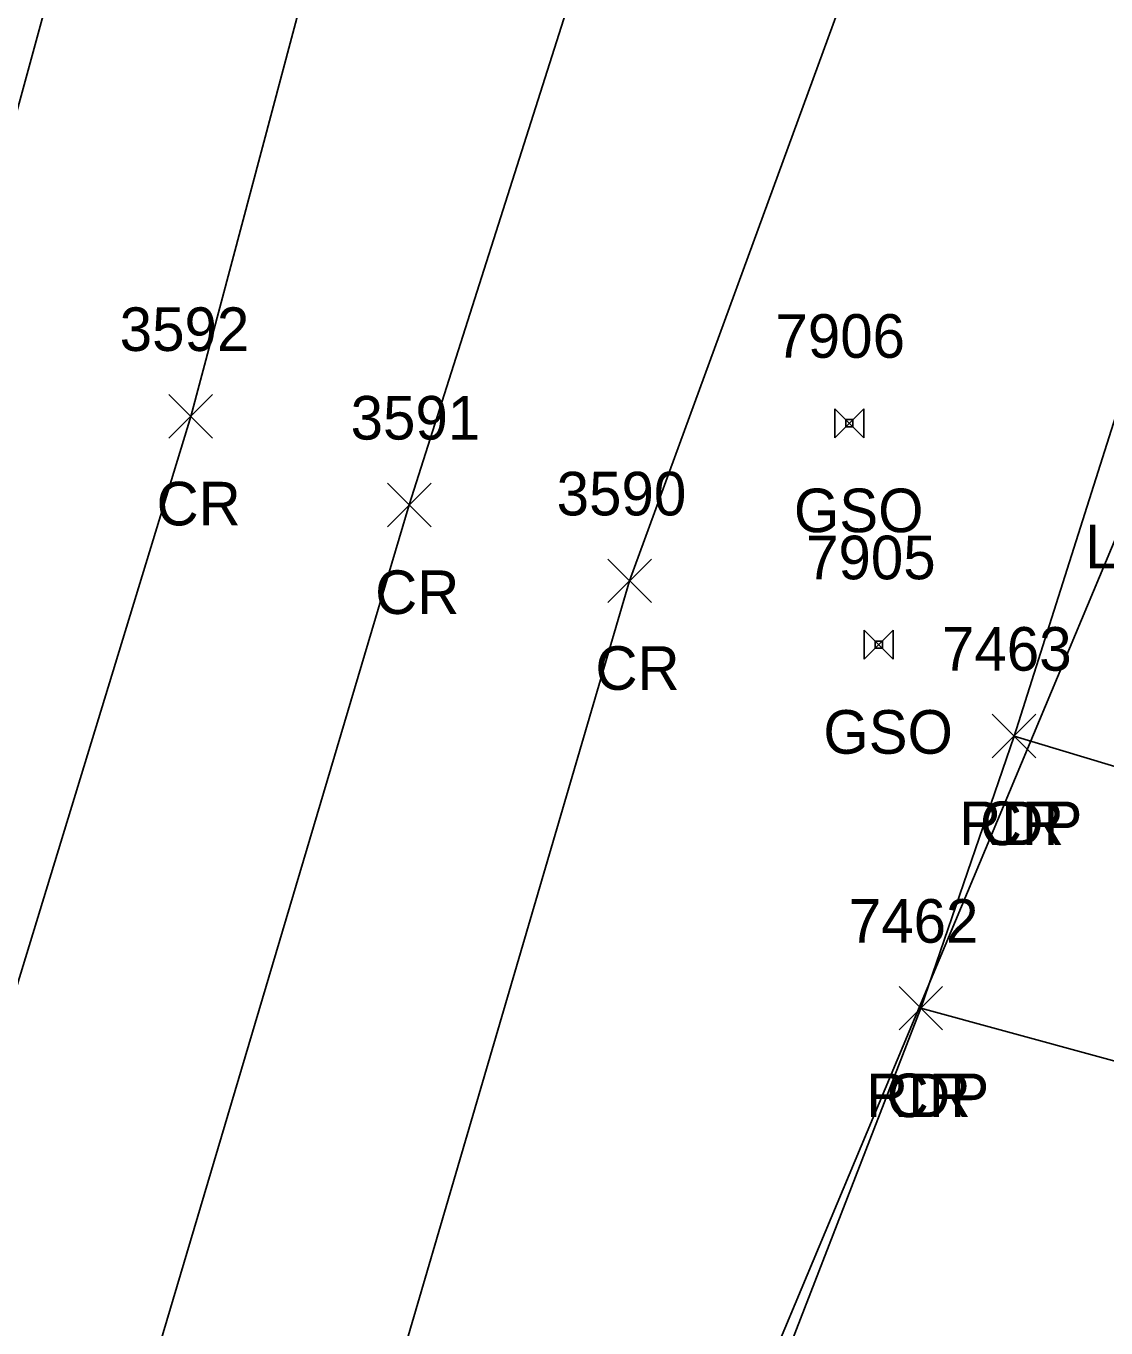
# Model space of a CAD drawing. Extents: x 1462089 to 1464015, y 730534 to 736144.
# Drawn here: x 1462888.4 to 1462938, y 732362.7 to 732422.4 of the extents above; entities that cross this region are included whole.
import ezdxf

# ---------------------------------------------------------------- set-up
doc = ezdxf.new("R2010")
doc.units = 0
for name, color, linetype in [('DCP', 7, 'Continuous'), ('P_A', 7, 'Continuous'), ('P_I', 7, 'Continuous'), ('P_TIC', 7, 'Continuous'), ('PET', 7, 'Continuous'), ('PRC', 7, 'Continuous'), ('S_C', 7, 'Continuous'), ('U_A', 7, 'Continuous'), ('U_I', 7, 'Continuous'), ('UGV', 7, 'Continuous')]:
    doc.layers.add(name, color=color, linetype=linetype)

msp = doc.modelspace()

# ---------------------------------------------------------------- linework, layer by layer
at = {"layer": 'DCP'}
msp.add_lwpolyline([(1462904.683, 732318.359), (1462942.289, 732408.157)], dxfattribs=at)
at = {"layer": 'P_TIC'}
for points in [[(1462894.983, 732403.526), (1462896.983, 732405.526)], [(1462896.983, 732403.526), (1462894.983, 732405.526)], [(1462894.983, 732403.526), (1462896.983, 732405.526)], [(1462896.983, 732403.526), (1462894.983, 732405.526)], [(1462905.012, 732399.463), (1462907.012, 732401.463)], [(1462907.012, 732399.463), (1462905.012, 732401.463)], [(1462905.012, 732399.463), (1462907.012, 732401.463)], [(1462907.012, 732399.463), (1462905.012, 732401.463)], [(1462915.118, 732395.984), (1462917.118, 732397.984)], [(1462917.118, 732395.984), (1462915.118, 732397.984)], [(1462915.118, 732395.984), (1462917.118, 732397.984)], [(1462917.118, 732395.984), (1462915.118, 732397.984)], [(1462932.758, 732388.862), (1462934.758, 732390.862)], [(1462934.758, 732388.862), (1462932.758, 732390.862)], [(1462932.758, 732388.862), (1462934.758, 732390.862)], [(1462934.758, 732388.862), (1462932.758, 732390.862)], [(1462928.482, 732376.385), (1462930.482, 732378.385)], [(1462930.482, 732376.385), (1462928.482, 732378.385)], [(1462928.482, 732376.385), (1462930.482, 732378.385)], [(1462930.482, 732376.385), (1462928.482, 732378.385)]]:
    msp.add_lwpolyline(points, dxfattribs=at)
at = {"layer": 'PET'}
msp.add_lwpolyline([(1462879.385, 732206.829), (1462892.219, 732254.305), (1462907.579, 732309.882), (1462913.989, 732337.713), (1462917.604, 732346.713), (1462929.482, 732377.385), (1462933.758, 732389.862), (1462941.672, 732414.763), (1462948.84, 732435.879), (1462965.82, 732486.157), (1462974.322, 732513.603), (1462985.987, 732551.34), (1462997.312, 732587.459), (1463010.568, 732628.542), (1463018.12, 732655.414), (1463023.478, 732670.997), (1463036.185, 732713.313)], dxfattribs=at)
at = {"layer": 'PRC'}
for points in [[(1463184.256, 733428.992), (1463177.497, 733386.208), (1463169.424, 733335.001), (1463162.872, 733301.128), (1463154.541, 733254.523), (1463145.288, 733216.479), (1463131.667, 733162.646), (1463112.818, 733093.24), (1463099.084, 733044.738), (1463082.496, 732993.09), (1463066.926, 732944.788), (1463054.224, 732905.139), (1463038.504, 732856.129), (1463025.084, 732814.554), (1463009.903, 732766.247), (1462997.491, 732727.734), (1462980.345, 732670.554), (1462968.817, 732637.254), (1462956.141, 732592.493), (1462943.226, 732555.631), (1462933.854, 732526.131), (1462921.414, 732485.157), (1462905.691, 732440.942), (1462895.983, 732404.526)], [(1463173.556, 733299.02), (1463165.514, 733252.575), (1463157.364, 733210.847), (1463147.481, 733159.84), (1463128.564, 733086.33), (1463116.128, 733039.218), (1463100.451, 732983.575), (1463087.947, 732938.839), (1463073.799, 732896.756), (1463059.596, 732849.778), (1463047.555, 732806.211), (1463032.361, 732758.169), (1463016.832, 732714.699), (1463001.87, 732663.361), (1462991.082, 732629.319), (1462977.348, 732584.698), (1462966.059, 732548.545), (1462956.48, 732518.599), (1462941.542, 732474.035), (1462928.099, 732429.753), (1462916.118, 732396.984)], [(1463154.541, 733254.523), (1463146.614, 733215.85), (1463135.444, 733161.471), (1463118.39, 733090.76), (1463105.826, 733042.869), (1463089.368, 732989.244), (1463076.43, 732943.443), (1463063.883, 732901.539), (1463049.781, 732852.757), (1463036.576, 732810.581), (1463021.663, 732763.563), (1463007.349, 732718.699), (1462991.106, 732667.436), (1462980.417, 732633.719), (1462966.431, 732588.152), (1462955.049, 732551.986), (1462945.505, 732521.937), (1462931.545, 732478.169), (1462917.136, 732435.424), (1462906.012, 732400.463)], [(1462985.716, 732731.928), (1462969.444, 732677.267), (1462957.486, 732641.208), (1462943.904, 732597.669), (1462931.653, 732559.608), (1462922.759, 732531.119), (1462910.18, 732489.033), (1462895.07, 732444.402), (1462885.161, 732408.132), (1462864.593, 732375.333), (1462853.42, 732347.258), (1462832.874, 732276.651), (1462823.233, 732232.908), (1462808.463, 732182.81), (1462796.537, 732136.818), (1462784.674, 732094.481), (1462773.756, 732052.904), (1462761.068, 732007.231), (1462748.947, 731961.516), (1462736.508, 731921.312)], [(1462895.983, 732404.526), (1462883.093, 732362.376), (1462876.352, 732338.992), (1462858.324, 732273.435), (1462845.774, 732225.609), (1462832.163, 732177.159), (1462820.065, 732130.658), (1462807.669, 732084.907), (1462796.727, 732044.248), (1462784.843, 732000.16), (1462772.409, 731954.341), (1462759.38, 731913.09)], [(1462906.012, 732400.463), (1462887.359, 732337.746)], [(1462916.118, 732396.984), (1462897.997, 732335.159), (1462879.045, 732267.64)], [(1462933.758, 732389.862), (1462981.203, 732375.569), (1463025.599, 732361.351), (1463057.397, 732350.23), (1463102.913, 732324.868)], [(1462929.482, 732377.385), (1462978.213, 732364.082), (1463022.056, 732350.159), (1463054.853, 732339.994), (1463102.913, 732324.868), (1463145.703, 732311.685), (1463172.464, 732303.441), (1463219.444, 732289.053), (1463245.294, 732280.954)]]:
    msp.add_lwpolyline(points, dxfattribs=at)
at = {"layer": 'UGV'}
for p, q in [((1462925.536, 732404.88), (1462926.869, 732403.547)), ((1462926.869, 732404.88), (1462925.536, 732403.547)), ((1462926.886, 732394.721), (1462928.219, 732393.388)), ((1462928.219, 732394.721), (1462926.886, 732393.388))]:
    msp.add_line(p, q, dxfattribs=at)
for points in [[(1462925.536, 732404.88), (1462925.536, 732403.547)], [(1462926.869, 732403.547), (1462926.869, 732404.88)], [(1462926.886, 732394.721), (1462926.886, 732393.388)], [(1462928.219, 732393.388), (1462928.219, 732394.721)]]:
    msp.add_lwpolyline(points, dxfattribs=at)
for points in [[(1462926.369, 732404.38), (1462926.036, 732404.38), (1462926.036, 732404.047), (1462926.369, 732404.047)], [(1462927.719, 732394.221), (1462927.386, 732394.221), (1462927.386, 732393.888), (1462927.719, 732393.888)]]:
    msp.add_lwpolyline(points, close=True, dxfattribs=at)

# ---------------------------------------------------------------- texts
at = {"layer": 'P_A'}
for s, p in [('CR', (1462894.416, 732399.526)), ('CR', (1462894.416, 732399.526)), ('CR', (1462904.445, 732395.463)), ('CR', (1462904.445, 732395.463)), ('CR', (1462914.551, 732391.984)), ('CR', (1462914.551, 732391.984)), ('RDP', (1462931.246, 732384.862)), ('CR', (1462932.191, 732384.862)), ('RDP', (1462926.97, 732372.385)), ('CR', (1462927.915, 732372.385))]:
    msp.add_text(s, height=2, dxfattribs=at).set_placement(p)
at = {"layer": 'P_I'}
for s, p in [('3592', (1462892.724, 732407.526)), ('3592', (1462892.724, 732407.526)), ('3591', (1462903.319, 732403.463)), ('3591', (1462903.319, 732403.463)), ('3590', (1462912.772, 732399.984)), ('3590', (1462912.772, 732399.984)), ('7463', (1462930.451, 732392.862)), ('7463', (1462930.451, 732392.862)), ('7462', (1462926.175, 732380.385)), ('7462', (1462926.175, 732380.385))]:
    msp.add_text(s, height=2, dxfattribs=at).set_placement(p)
at = {"layer": 'S_C'}
msp.add_text('LOWER MTN VIEW DR', height=2, dxfattribs=at).set_placement((1462937.019, 732397.556))
at = {"layer": 'U_A'}
for p in [(1462923.659, 732399.214), (1462925.009, 732389.055)]:
    msp.add_text('GSO', height=2, dxfattribs=at).set_placement(p)
at = {"layer": 'U_I'}
for s, p in [('7906', (1462922.809, 732407.214)), ('7905', (1462924.214, 732397.055))]:
    msp.add_text(s, height=2, dxfattribs=at).set_placement(p)

doc.saveas('drawing.dxf')
